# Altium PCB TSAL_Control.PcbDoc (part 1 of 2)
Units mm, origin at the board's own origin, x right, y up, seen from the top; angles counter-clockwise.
Board outline 110 x 55.6 mm, 4 copper layers (Top Layer, GND, PWR, Bottom Layer), stack 1.488 mm thick; 121 components, 67 nets, 352 pads, 66 vias.
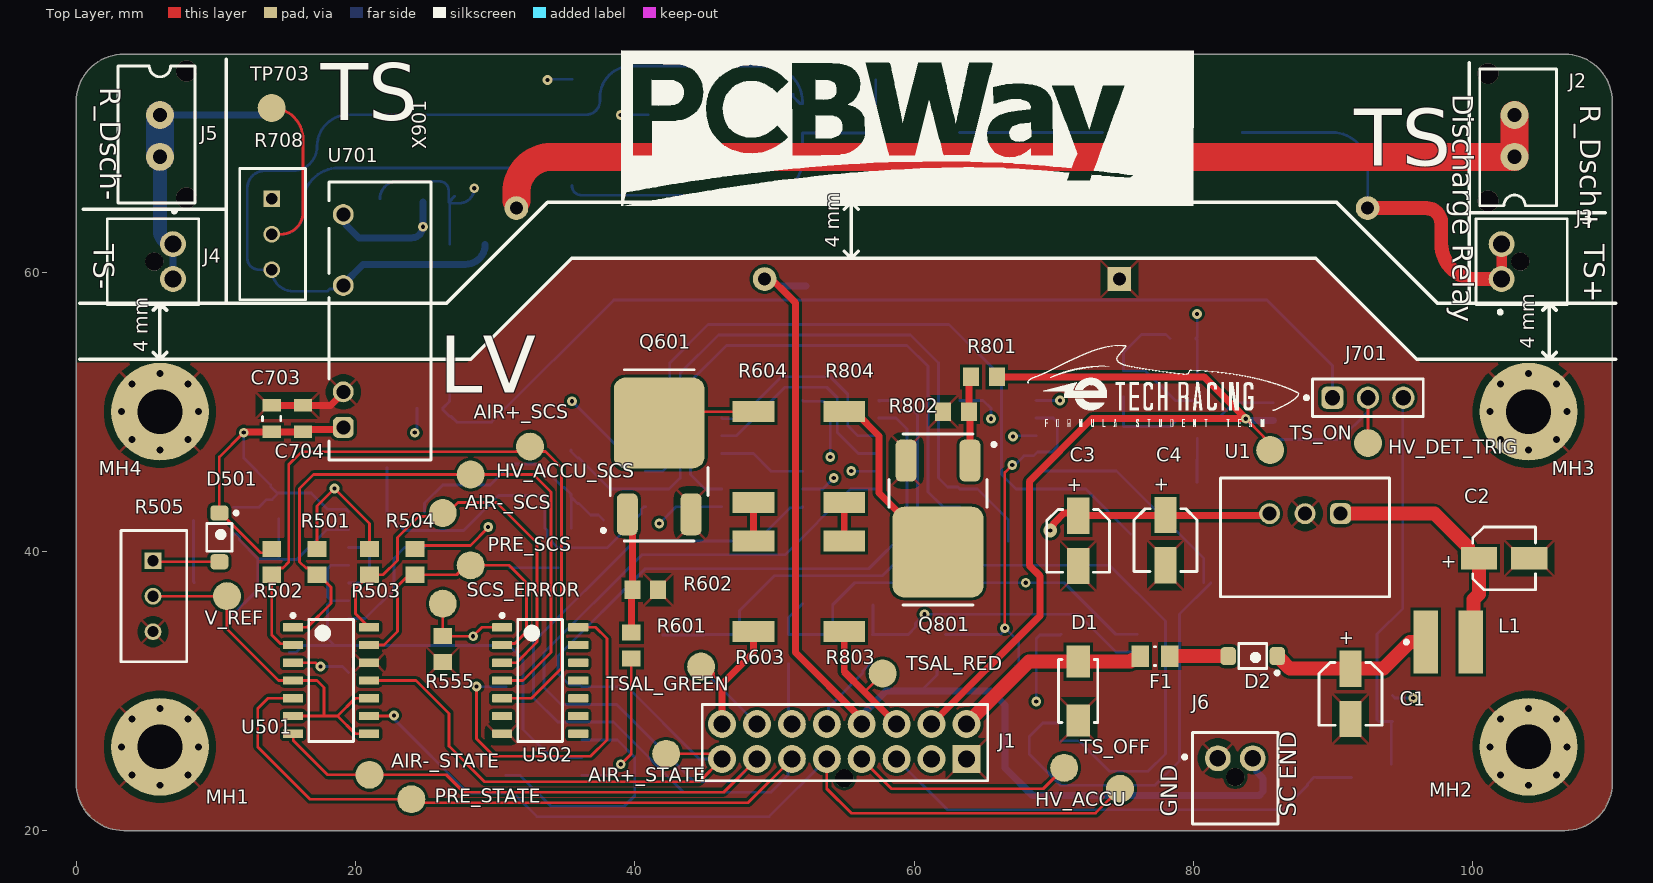
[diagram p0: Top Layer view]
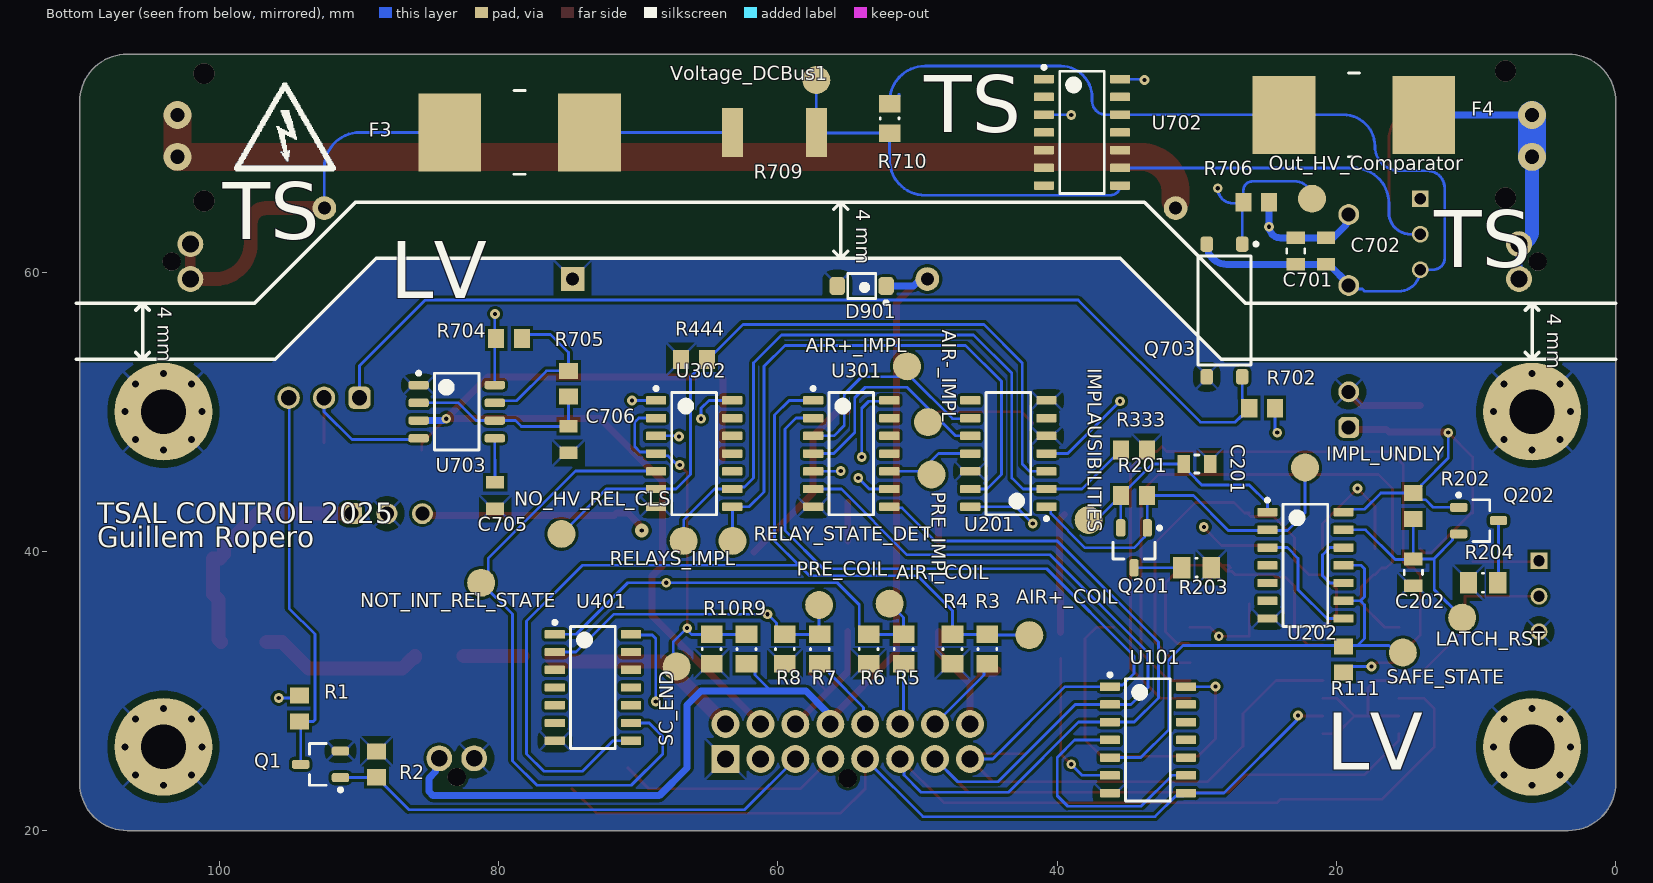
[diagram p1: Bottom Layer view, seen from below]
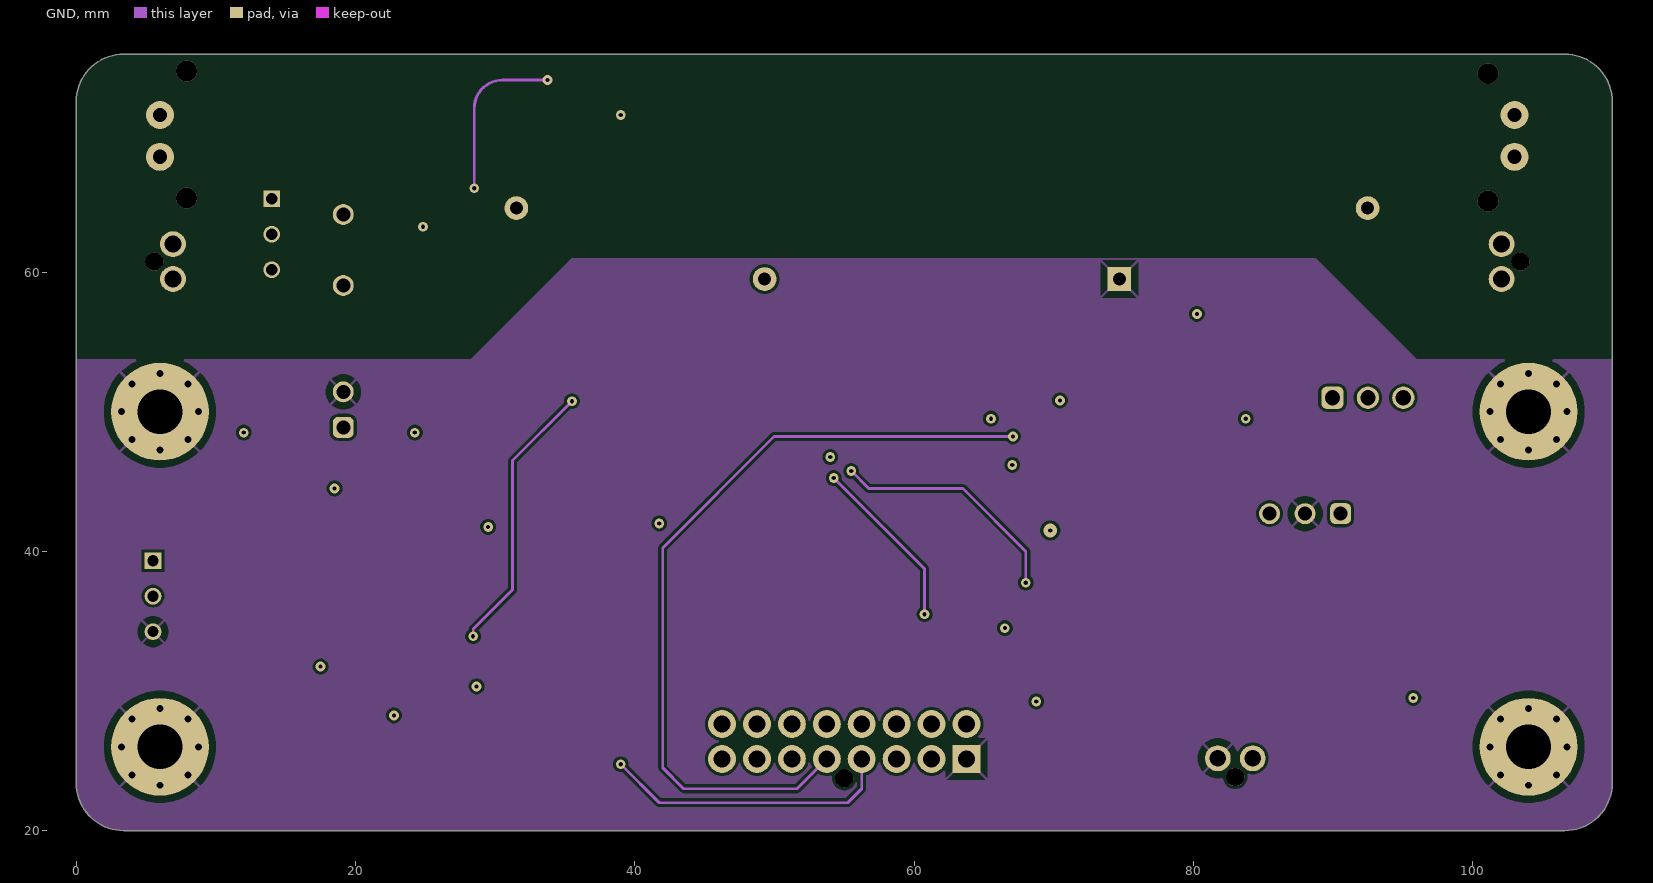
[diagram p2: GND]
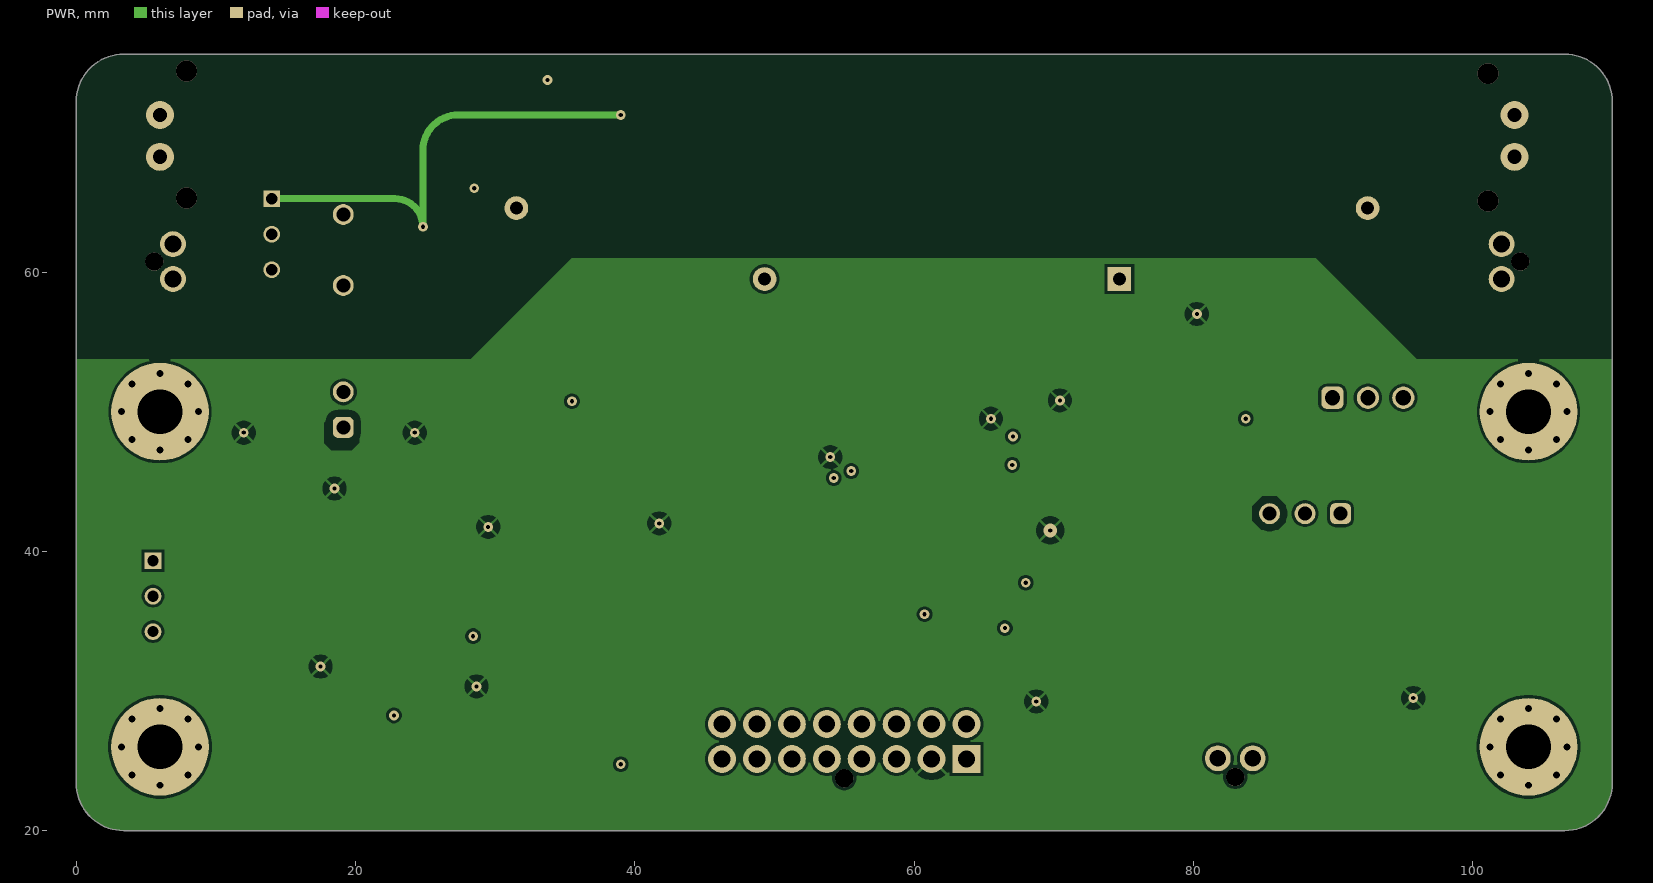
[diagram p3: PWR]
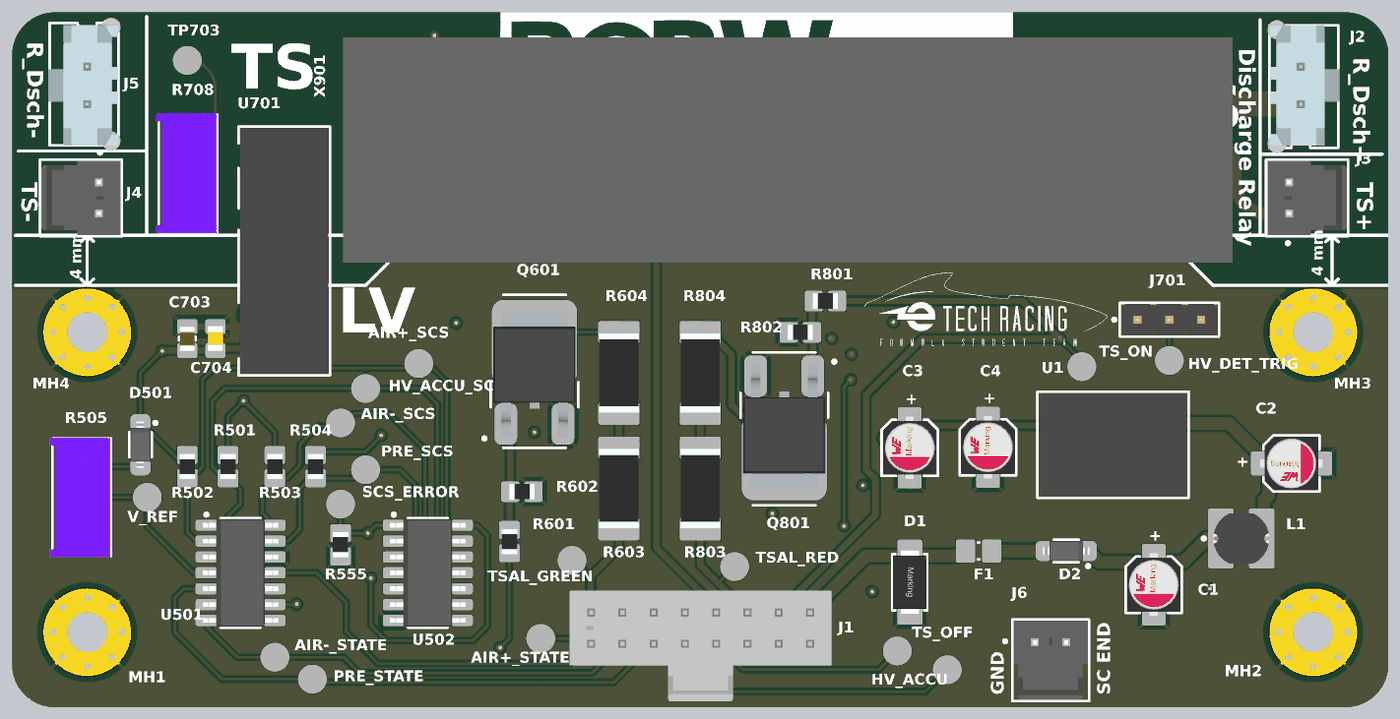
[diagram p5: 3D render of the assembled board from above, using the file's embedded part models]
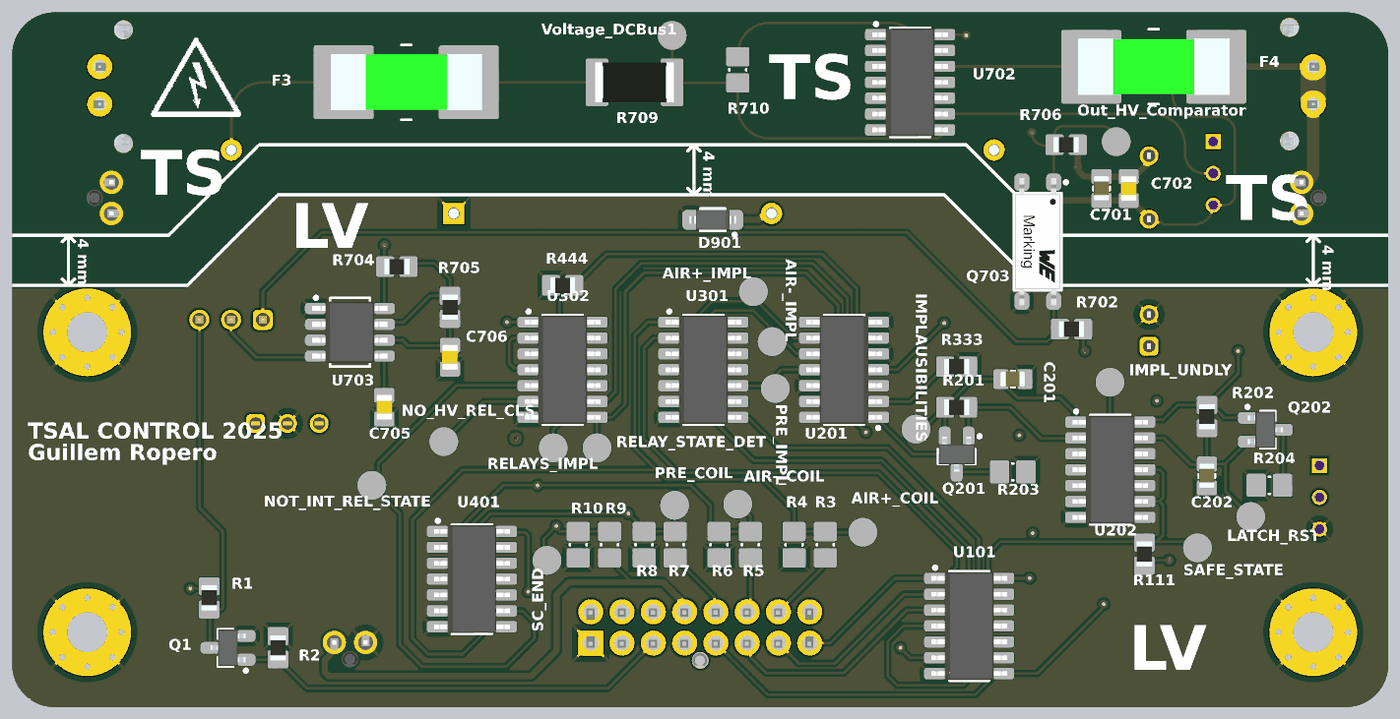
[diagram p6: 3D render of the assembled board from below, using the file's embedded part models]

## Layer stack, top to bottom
Top Solder: solder mask 0.01, Solder Resist, Dk 3.5
Top Layer: signal copper 0.035
Dielectric 2: prepreg 0.1, PP-006, Dk 4.1
GND: signal copper 0.009
Dielectric 6: prepreg 0.1, PP-006, Dk 4.1
Dielectric 1: dielectric 1, FR-4, Dk 4.8
Dielectric 7: prepreg 0.1, PP-006, Dk 4.1
PWR: signal copper 0.009
Dielectric 3: prepreg 0.1, PP-006, Dk 4.1
Bottom Layer: signal copper 0.035
Bottom Solder: solder mask 0.01, Solder Resist, Dk 3.5

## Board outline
0,23.414 0,72 0,72.186 cw(c3.414,72.186) 3.414,75.6 106.5,75.6 106.586,75.6 cw(c106.586,72.186) 110,72.186 110,72 110,23.414 cw(c106.586,23.414) 106.586,20 106.5,20 3.414,20 cw(c3.414,23.414)

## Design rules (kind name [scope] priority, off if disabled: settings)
Clearance Clearance_TS-LVS [InNetClass('TS') vs InNetClass('LVS')] p1: gap=4 ignorepadtopadclearanceinfootprint=FALSE
Clearance Clearance_std [All] p2: gap=0.2 ignorepadtopadclearanceinfootprint=FALSE
ComponentClearance [All] p1: gap=0.2 collisioncheckmode=3 verticalgap=0.2 showdistances=FALSE
HoleSize [All] p1: absolutevalues=TRUE maxlimit=4 minlimit=0.2 maxpercent=80.000 minpercent=20.000
PasteMaskExpansion [All] p1: expansion=0.15
PlaneClearance [All] p1: clearance=0.5
PlaneConnect [All] p1: planeconnectstyle=Relief reliefexpansion=0.5 reliefentries=4 reliefconductorwidth=0.2 reliefairgap=0.2
PolygonConnect [All] p1: connectstyle=Relief reliefconductorwidth=0.2 reliefentries=4 polygonreliefangle="45 Angle" airgapwidth=0.5
RoutingVias [All] p1: holewidth=0.3 width=0.7 viastyle="Through Hole" minholewidth=0.2 minwidth=0.5 maxholewidth=4 maxwidth=8
SilkToSilkClearance [All] p1: silktosilkclearance=0
SilkToSolderMaskClearance [IsPad] p1: minsilkscreentomaskgap=0.1 clearancetoexposedcopper=TRUE
SolderMaskExpansion [All] p1: expansion=0.1 istentingtop=FALSE
UnRoutedNet [All] p1: checkbadconnections=TRUE
Width [All] p1: maxlimit=3 minlimit=0.2 preferedwidth=0.5
22 further rules are at their usual default settings.

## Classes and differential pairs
component class Discharge_circuit: D901 X901
component class "TSAL Red": C701 C702 C703 C704 C705 C706 HV_DET_TRIG J701 Out_HV_Comparator Q703 R702 R704 R705 R706 R708 R709 R710 TP703 TS_ON U701 U702 U703 Voltage_DCBus1
component class "TSAL Green": AIR+_COIL AIR+_STATE AIR-_COIL AIR-_STATE HV_ACCU PRE_COIL PRE_STATE R111 SC_END TS_OFF U101
component class "Relay Implausibility": AIR+_IMPL AIR-_IMPL PRE_IMPL R333 RELAY_STATE_DET RELAYS_IMPL U301 U302
component class "Red Driver": Q801 R801 R802 R803 R804 TSAL_RED
component class Implausibilities: C201 C202 IMPL_UNDLY IMPLAUSIBILITIES LATCH_RST Q201 Q202 R201 R202 R203 R204 SAFE_STATE U201 U202
component class TSAL_Control: C1 C2 C3 C4 D1 D2 F1 F3 F4 F_DC_BUS1 F_DC_BUS? F_TS-? J1 J2 J3 J4 J5 J6 J_TS+_DC_BUS1 J_TS+_DC_BUS? J_TS- L1 MH1 MH2 MH3 MH4 Q1 R1 R2 R3 R4 R5 R6 R7 R8 R9 R10 U1
component class SCS: AIR+_SCS AIR-_SCS D501 HV_ACCU_SCS PRE_SCS R501 R502 R503 R504 R505 R555 SCS_ERROR U501 U502 V_REF
component class "EV 4.10.14": NO_HV_REL_CLS NOT_INT_REL_STATE R444 U401
component class "Green Driver": Q601 R601 R602 R603 R604 TSAL_GREEN

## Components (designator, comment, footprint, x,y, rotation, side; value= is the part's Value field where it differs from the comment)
AIR+_COIL "TestPoint" TestPoint 42,34 r90 bottom (schematic designator TP106)
AIR+_IMPL "TestPoint" TestPoint 50.75,53.25 r90 bottom (schematic designator TP301)
AIR+_SCS "TestPoint" TestPoint 32.5,47.5 r90 top (schematic designator TP503)
AIR+_STATE "TestPoint" TestPoint 42.25,25.5 r90 top (schematic designator TP102)
AIR-_COIL "TestPoint" TestPoint 52,36.25 r90 bottom (schematic designator TP108)
AIR-_IMPL "TestPoint" TestPoint 49.25,49.25 r90 bottom (schematic designator TP302)
AIR-_SCS "TestPoint" TestPoint 26.25,42.75 r90 top (schematic designator TP504)
AIR-_STATE "TestPoint" TestPoint 21,24 r90 top (schematic designator TP104)
C1 "C10u-35V-Electrolytic" 865080540004-Footprint-1 91.25,29.8 r90 top value=10µF
C2 "C10u-35V-Electrolytic" 865080540004-Footprint-1 102.25,39.5 r180 top value=10µF
C3 "C10u-35V-Electrolytic" 865080540004-Footprint-1 71.75,40.75 r90 top value=10µF
C4 "C10u-35V-Electrolytic" 865080540004-Footprint-1 78,40.8 r90 top value=10µF
C201 "C10u-16V-0805FNPC-X5R" C0805FNPC-R 30,46.25 r180 bottom value=10µF
C202 "C10u-16V-0805FNPC-X5R" C0805FNPC-R 14.5,38.5 r270 bottom value=10µF
C701 "C1u-50V-0805FNPC-X7R" C0805FNPC-R 22.921,61.5 r270 bottom value=1µF
C702 "C100n-16V-0805" WCAP-CSGP_0805_L2W1.25H0.8_Reflow 20.75,61.5 r270 bottom
C703 "C1u-50V-0805FNPC-X7R" C0805FNPC-R 14,49.5 r90 top value=1µF
C704 "C100n-16V-0805" WCAP-CSGP_0805_L2W1.25H0.8_Reflow 16.25,49.5 r90 top
C705 "C100n-16V-0805" WCAP-CSGP_0805_L2W1.25H0.8_Reflow 80.25,44 r270 bottom value=100nF
C706 "C22u-25V-0805" WCAP-CSGP_0805_L2W1.25H0.8_Reflow 75,48 r270 bottom value=22uF
D1 "TVS_33V_400W" WE-TVSP_DO-214AC_Bidirectional 71.75,30 r270 top
D2 "DSC-0.5/30-SOD123" DSC-SOD123 84.25,32.5 r180 top
D501 "DZ-0.01/75-SOD-123" DSC-SOD123 10.25,41 r270 top
D901 "DSC-0.5/30-SOD123" DSC-SOD123 54,59 r0 bottom
F1 "MFU0805FF00500P500" 0805 77.25,32.5 r270 top value=0.5A-50V
F3 "Fuse_1A_600V" Fuse_485001 78.5,70 r0 bottom
F4 "Fuse_1A_600V" Fuse_485001 18.75,71.25 r180 bottom
HV_ACCU "TestPoint" TestPoint 74.75,23 r90 top (schematic designator TP105)
HV_ACCU_SCS "TestPoint" TestPoint 28.25,45.5 r90 top (schematic designator TP502)
HV_DET_TRIG "TestPoint" TestPoint 92.5,47.75 r90 top (schematic designator TP704)
IMPL_UNDLY "TestPoint" TestPoint 22.25,46 r90 bottom (schematic designator TP201)
IMPLAUSIBILITIES "TestPoint" TestPoint 37.75,42.25 r90 bottom (schematic designator TP202)
J1 "J_NanoFit_2x8_V" J_NanoFit_2x8_V 55,30 r180 top
J2 "J_MicroFit_2x1" J_MicroFit_2x1 103,68.25 r270 top
J3 "J_NanoFit_1x2" FP-105309-1102-MFG 103.5,60.75 r90 top
J4 "J_NanoFit_1x2" FP-105309-1102-MFG 5.5,60.75 r270 top
J5 "J_MicroFit_2x1" J_MicroFit_2x1 6,71.25 r90 top
J6 "J_NanoFit_1x2" FP-105309-1102-MFG 83,23.75 r0 top
J701 "3Pin-Pinheader" 61300311121 92.5,51 r0 top
L1 "7447730" WE-PD2_4532 98.25,33.5 r0 top value=1uH
LATCH_RST "TestPoint" TestPoint 11,35.25 r90 bottom (schematic designator TP203)
MH1 "Mounting_Hole_M3" Mounting_Hole_M3 6,26 r0 top
MH2 "Mounting_Hole_M3" Mounting_Hole_M3 104,26 r0 top
MH3 "Mounting_Hole_M3" Mounting_Hole_M3 104,50 r0 top
MH4 "Mounting_Hole_M3" Mounting_Hole_M3 6,50 r0 top
NO_HV_REL_CLS "TestPoint" TestPoint 75.5,41.25 r180 bottom (schematic designator TP402)
NOT_INT_REL_STATE "TestPoint" TestPoint 81.25,37.75 r90 bottom (schematic designator TP401)
Out_HV_Comparator "TestPoint" TestPoint 21.75,65.25 r90 bottom (schematic designator TP702)
PRE_COIL "TestPoint" TestPoint 57.05,36.158 r90 bottom (schematic designator TP107)
PRE_IMPL "TestPoint" TestPoint 49,45.5 r90 bottom (schematic designator TP303)
PRE_SCS "TestPoint" TestPoint 28.25,39 r90 top (schematic designator TP505)
PRE_STATE "TestPoint" TestPoint 24,22.25 r90 top (schematic designator TP103)
Q1 "TRT-NCH-8/40-SQ" TRT-NCH-3/35-CPH 92.75,24.75 r0 bottom
Q201 "TRT-PCH-2/30-BSS" TRT-PCH-2/30-BSS 34.5,40.25 r270 bottom
Q202 "TRT-PCH-2/30-BSS" TRT-PCH-2/30-BSS 9.825,42.2 r180 bottom
Q601 "TRT-NCH-31/100" TRT-NCH-D2PAK 41.75,46.75 r0 top
Q703 "Optocoupler" WL-OCPT_LSOP4 28.02,57.25 r270 bottom
Q801 "TRT-NCH-31/100" TRT-NCH-D2PAK 61.714,42.4 r180 top
R1 "R10k-0805FTK" R0805FTK 94.25,28.75 r270 bottom value=10k
R2 "R10k-0805FTK" R0805FTK 88.75,24.75 r90 bottom value=10k
R3 "R12K4-0805-0.125W" 0805 45,33 r180 bottom value=12.4k
R4 "R8.2K_0805_0.125W" 0805 47.5,33 r0 bottom value=8.2k
R5 "R12K4-0805-0.125W" 0805 51,33 r180 bottom value=12.4k
R6 "R8.2K_0805_0.125W" 0805 53.5,33 r0 bottom value=8.2k
R7 "R12K4-0805-0.125W" 0805 57,33 r180 bottom value=12.4k
R8 "R8.2K_0805_0.125W" 0805 59.5,33 r0 bottom value=8.2k
R9 "R12K4-0805-0.125W" 0805 62.25,33 r180 bottom value=12.4k
R10 "R8.2K_0805_0.125W" 0805 64.75,33 r0 bottom value=8.2k
R111 "R470-0805FTK" R0805FTK 19.5,32.25 r270 bottom value=470
R201 "R10k-0805FTK" R0805FTK 34.5,44 r0 bottom value=10k
R202 "R10k-0805FTK" R0805FTK 14.5,43.25 r270 bottom value=10k
R203 "R1K-0805-0.5W" 0805 30.021,38.829 r270 bottom value=1k
R204 "R1K-0805-0.5W" 0805 9.5,37.75 r90 bottom value=1k
R333 "R470-0805FTK" R0805FTK 34.5,47.25 r0 bottom value=470
R444 "R470-0805FTK" R0805FTK 66,53.75 r180 bottom value=470
R501 "R1k-0805FTK" R0805FTK 17.25,39.25 r270 top value=1k
R502 "R1k-0805FTK" R0805FTK 14,39.25 r270 top value=1k
R503 "R1k-0805FTK" R0805FTK 21,39.25 r270 top value=1k
R504 "R1k-0805FTK" R0805FTK 24.25,39.25 r270 top value=1k
R505 "R1k-VTR" R1k-VTR 5.5,36.79 r0 top value=1k
R555 "R470-0805FTK" R0805FTK 26.25,33 r90 top value=470
R601 "R100-0805FTK" R0805FTK 39.75,33.25 r90 top value=100
R602 "R1k-0805FTK" R0805FTK 40.75,37.25 r0 top value=1k
R603 "R15_3521_2W" R_3521 48.5,37.5 r90 top value=15
R604 "R15_3521_2W" R_3521 48.5,46.75 r90 top value=15
R702 "R10k-0805FTK" R0805FTK 25.325,50.25 r0 bottom value=10k
R704 "R100-0805FTK" R0805FTK 79.25,55.25 r180 bottom value=100
R705 "R10k-0805FTK" R0805FTK 75,52 r270 bottom value=10k
R706 "R10k-0805FTK" R0805FTK 25.75,65 r0 bottom value=10k
R708 "R10k-VTR" R10k-VTR 14,62.71 r0 top value=10k
R709 "R2M-2512FTK" R2512FTK 60.25,70 r180 bottom
R710 "R51k_0805" 0805 52,71 r180 bottom value=51k
R801 "R100-0805FTK" R0805FTK 65,52.5 r180 top value=100
R802 "R1k-0805FTK" R0805FTK 63,50 r180 top value=1k
R803 "R15_3521_2W" R_3521 55,37.5 r90 top value=15
R804 "R15_3521_2W" R_3521 55,46.75 r90 top value=15
RELAY_STATE_DET "TestPoint" TestPoint 63.25,40.75 r90 bottom (schematic designator TP304)
RELAYS_IMPL "TestPoint" TestPoint 66.75,40.75 r90 bottom (schematic designator TP305)
SAFE_STATE "TestPoint" TestPoint 15.25,32.75 r90 bottom (schematic designator TP204)
SC_END "TestPoint" TestPoint 67.25,31.75 r90 bottom (schematic designator TP109)
SCS_ERROR "TestPoint" TestPoint 26.25,36.25 r90 top (schematic designator TP506)
TP703 "TestPoint" TestPoint 14,71.75 r90 top
TS_OFF "TestPoint" TestPoint 70.75,24.5 r90 top (schematic designator TP101)
TS_ON "TestPoint" TestPoint 85.5,47.25 r90 top (schematic designator TP701)
TSAL_GREEN "TestPoint" TestPoint 44.75,31.75 r90 top (schematic designator TP601)
TSAL_RED "TestPoint" TestPoint 57.75,31.25 r90 top (schematic designator TP801)
U1 "DCDC-36V/12V-1A" WPME-FDSM_SIP-3_L11.6W8H10.4 88,41 r180 top
U101 "CD4073BM" D0014A_N 33.5,26.5 r180 bottom
U201 "CD4072BM" D0014A_N 43.5,47 r0 bottom
U202 "CD4011BM" D0014A_N 22.225,39 r180 bottom
U301 "CD4070BM" D0014A_N 54.75,47 r180 bottom
U302 "CD4073BM" D0014A_N 66,47 r180 bottom
U401 "CD4023BM" D0014A_N 73.25,30.25 r180 bottom
U501 "LM339D" D0014A_N 18.25,30.75 r0 top
U502 "CD4072BM" D0014A_N 33.225,30.75 r0 top
U701 "DCDC_ISO_12VIN_5VOUT" WPME-FISM_SIP-7_L19.65W7.05H10.16 21.75,56.5 r90 top
U702 "LM339D" D0014A_N 38.225,70 r180 bottom
U703 "Timer_SA555" Timer_SA555 83,50 r180 bottom
V_REF "TestPoint" TestPoint 10.798,36.79 r90 top (schematic designator TP501)
Voltage_DCBus1 "TestPoint" TestPoint 57.25,73.75 r90 bottom (schematic designator TP705)
X901 "HV-Relay-SPST-NC-24V" HV-Relay-SPST-NC-24V 31.52,64.58 r0 top

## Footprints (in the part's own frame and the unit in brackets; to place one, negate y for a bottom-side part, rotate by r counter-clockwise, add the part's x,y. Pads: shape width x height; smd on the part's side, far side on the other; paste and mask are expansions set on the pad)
0805 [mm] "Chip Resistor, 2-Leads, Body 2,60x1,50mm, IPC Medium Density"
  rect 1.55x1.25 smd: 1(0,-1.05) 2(0,1.05)
  silkscreen extent -0.67,-0.05 0.67,0.05, body extent -0.75,-1.3 0.75,1.3, height 0.6
61300311121 [mm] "Pin Header, pitch 2.54 mm, THT, Vertical, single row, 3p"
  rrect50% 1.6x1.6 hole 1.1: 1(-2.54,0)
  round 1.6 hole 1.1: 2(0,0) 3(2.54,0)
  silkscreen extent -4.53,-1.35 3.96,1.35, body extent -3.81,-1.27 3.81,1.27, height 8.57
865080540004-Footprint-1 [mm]
  rect 2.6x1.6 smd: 1(1.8,0) 2(-1.8,0)
  silkscreen extent -2.25,-2.25 2.25,2.25, body extent -2.5,-2.15 2.5,2.15, height 5.5
C0805FNPC-R [mm]
  rect 0.9x1.3 smd: 1(-0.95,0) 2(0.95,0)
  silkscreen extent -0.15,-0.65 0.15,0.65, body extent -1.03,-0.63 0.97,0.63, height 0.96
D0014A_N [mm] "SOIC, 14-Leads, Body 8.75x4mm, Pitch 1.27mm, IPC Medium Density"
  rrect17% 1.45x0.6 smd: 1(-2.725,3.81) 2(-2.725,2.54) 3(-2.725,1.27) 4(-2.725,0) 5(-2.725,-1.27) 6(-2.725,-2.54) 7(-2.725,-3.81) 8(2.725,-3.81) 9(2.725,-2.54) 10(2.725,-1.27) 11(2.725,0) 12(2.725,1.27) 13(2.725,2.54) 14(2.725,3.81)
  silkscreen extent -2.85,-4.38 1.6,4.78, body extent -3.02,-4.32 3.02,4.32, height 1.59
DSC-SOD123 [mm] "SOIC, 2-Leads, Body 1,60x2,69mm, Pitch 1,27mm, IPC Low Density"
  rrect50% 1.1x1.3 smd: A(1.75,0) K(-1.75,0)
  silkscreen extent -1.88,-0.9 1,1.32, body extent -1.86,-0.8 1.86,0.8, height 1.36
FP-105309-1102-MFG [mm]
  round 1.85 hole 1.2 paste-2539.97 mask+0: 1(-1.25,1.43) 2(1.25,1.43)
  round 1.3 hole 1.3 unplated paste-2539.97 mask+0: ""(0,0.09)
  silkscreen extent -3.75,-3.27 3.07,3.27, body extent -3.17,-3.37 3.17,3.37, height 0.25
Fuse_485001 [mm]
  rect 4.5x5.6 smd: 1(-5,0) 2(5,0)
  silkscreen extent -0.4,-3 0.4,3, body extent -6.05,-2.25 6.05,2.25, height 4.5
HV-Relay-SPST-NC-24V [mm]
  round 1.7 hole 0.94: 1(0,0) 2(17.78,-5.08) 4(60.96,0)
  rect 1.7x1.7 hole 0.94: 3(43.18,-5.08)
  body extent -5.08,-9.02 66.04,9.01, height 19.15
J_MicroFit_2x1 [mm]
  round 2 hole 1.02: 1(0,0) 2(-3,0)
  silkscreen extent -6.3,-2.5 3.5,3, body extent -6.32,-2.47 3.32,3.1, height 10
J_NanoFit_2x8_V [mm]
  round 2 hole 1.2: 1(8.75,4.87) 2(6.25,4.87) 3(3.75,4.87) 4(1.25,4.87) 5(-1.25,4.87) 6(-3.75,4.87) 7(-6.25,4.87) 9(8.75,2.369) 10(6.25,2.369) 11(3.75,2.369) 12(1.25,2.369) 13(-1.25,2.369) 14(-3.75,2.369) 15(-6.25,2.369) 16(-8.75,2.369)
  rect 2x2 hole 1.2: 8(-8.75,4.87)
  round 1.3 hole 1.3: A(0,6.25)
  silkscreen extent -10.27,0.97 10.17,6.43, body extent -10.5,0.68 10.44,9.53, height 10.18
Mounting_Hole_M3 [mm]
  round 7 hole 3.2: 1(0,0)
R1k-VTR [mm]
  rect 1.2x1.2 hole 0.8: 1(0,2.54)
  round 1.2 hole 0.8: 2(0,-2.54) 3(0,0)
  silkscreen extent -2.29,-4.7 2.41,4.7, body extent -2.49,-4.78 2.34,4.78, height 11.09
R10k-VTR [mm]
  rect 1.2x1.2 hole 0.8: 1(0,2.54)
  round 1.2 hole 0.8: 2(0,-2.54) 3(0,0)
  silkscreen extent -2.29,-4.7 2.41,4.7, body extent -2.49,-4.78 2.34,4.78, height 11.09
R0805FTK [mm] "Chip Resistor, 2-Leads, Body 2,00x1,25mm, IPC Medium Density"
  rect 1.15x1.35 smd: 1(-0.925,0) 2(0.925,0)
  body extent -1,-0.63 1,0.63, height 0.65
R2512FTK [mm]
  rect 1.5x3.5 smd: 1(-3,0) 2(3,0)
  body extent -3.15,-1.6 3.15,1.6, height 0.66
R_3521 [mm]
  rect 1.5x3 smd: 1(-3.25,0) 2(3.25,0)
  body extent -3.17,-1.6 3.17,1.6, height 0.65
TestPoint [mm]
  round 2 smd: 1(0,0)
Timer_SA555 [mm] "SOIC, 8-Leads, Body 4,90x3,90mm, Pitch 1,27mm, IPC Medium Density"
  rrect50% 1.45x0.6 smd: 1(-2.725,1.905) 2(-2.725,0.635) 3(-2.725,-0.635) 4(-2.725,-1.905) 5(2.725,-1.905) 6(2.725,-0.635) 7(2.725,0.635) 8(2.725,1.905)
  silkscreen extent -2.85,-2.75 1.6,2.88, body extent -3.01,-2.45 3.01,2.45, height 1.63
TRT-NCH-3/35-CPH [mm] "SOT23, 3-Leads, Body 2,90x2,80mm, Pitch 0,95mm, IPC Low Density"
  rrect50% 1.25x0.65 smd: D(1.425,0) G(-1.425,0.95) S(-1.425,-0.95)
  silkscreen extent -1.55,-1.5 0.8,1.95, body extent -1.4,-1.45 1.4,1.45, height 1.06
TRT-NCH-D2PAK [mm] "SOT23, 3-Leads, Body 2,90x2,80mm, Pitch 0,95mm, IPC Low Density"
  rrect25% 6.5x6.5 smd: D(0,2.45)
  rrect50% 1.5x3 smd: G(-2.286,-4.1) S(2.286,-4.1)
  silkscreen extent -4.12,-6 3.5,6.25, body extent -3.29,-5.12 3.29,4.8, height 2.29
TRT-PCH-2/30-BSS [mm] "SOT23, 3-Leads, Body 2,90x2,80mm, Pitch 0,95mm, IPC Low Density"
  rrect50% 1.25x0.65 smd: D(1.425,0) G(-1.425,0.95) S(-1.425,-0.95)
  silkscreen extent -1.55,-1.5 0.8,1.95, body extent -1.4,-1.45 1.4,1.45, height 1.06
WCAP-CSGP_0805_L2W1.25H0.8_Reflow [mm] "Ceramic Capacitors, body 2x1.25mm"
  rect 0.9x1.3 smd: 1(-0.95,0) 2(0.95,0)
  body extent -1,-0.62 1,0.63, height 0.8
WE-PD2_4532 [mm] "SMD Power Inductor, 2-Leads, body 4.5x4mm"
  rect 1.75x4.5 smd: 1(-1.625,0) 2(1.625,0)
  silkscreen extent -3.12,-0.12 -2.87,0.12, body extent -2.25,-2 2.25,2, height 3.22
WE-TVSP_DO-214AC_Bidirectional [mm] "Power TVS Diode, 2-Leads. body 4.24x2.67mm"
  rect 2.3x1.7 smd: 1(-2.1,0) 2(2.1,0)
  silkscreen extent -2.25,-1.4 2.25,1.4, body extent -2.56,-1.33 2.56,1.34, height 2.24
WL-OCPT_LSOP4 [mm] "Optocoupler Phototransistor, body 7.6x3.6mm"
  rrect50% 1.1x0.9 smd: 1(-4.75,1.27) 2(-4.75,-1.27) 3(4.75,-1.27) 4(4.75,1.27)
  silkscreen extent -4.87,-1.9 3.9,2.37, body extent -5.1,-1.8 5.1,1.8, height 2.1
WPME-FDSM_SIP-3_L11.6W8H10.4 [mm] "Fixed Step Down Regulator Module, SIP-3, body 11.60x80mm"
  rrect50% 1.5x1.5 hole 1: 1(-2.54,-1.7)
  round 1.5 hole 1: 2(0,-1.7) 3(2.54,-1.7)
  silkscreen extent -6.05,-4.25 6.05,4.25, body extent -5.8,-4 5.8,4, height 10.45
WPME-FISM_SIP-7_L19.65W7.05H10.16 [mm] "Power Module, SIP7, body 19.65x7.05mm"
  rrect50% 1.5x1.5 hole 1 paste-0.1: 1(-7.62,2.625)
  round 1.5 hole 1 paste-0.1: 2(-5.08,2.625) 3(2.54,2.625) 4(7.62,2.625)
  silkscreen extent -9.95,-3.65 9.95,3.65, body extent -9.82,-3.52 9.82,3.52, height 10.16

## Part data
AIR+_COIL AIR+_IMPL AIR+_SCS AIR+_STATE AIR-_COIL AIR-_IMPL AIR-_SCS AIR-_STATE HV_ACCU HV_ACCU_SCS HV_DET_TRIG IMPL_UNDLY IMPLAUSIBILITIES LATCH_RST NO_HV_REL_CLS NOT_INT_REL_STATE Out_HV_Comparator PRE_COIL PRE_IMPL PRE_SCS PRE_STATE RELAY_STATE_DET RELAYS_IMPL SAFE_STATE SC_END SCS_ERROR TP703 TS_OFF TS_ON TSAL_GREEN TSAL_RED V_REF Voltage_DCBus1: library part CMP-00042-1, "Test Point 1x1 mm"
C1 C2 C3 C4: library part CMP-001-00019-3, "WCAP-ASLI Aluminum Electrolytic Capacitors", Case/Package=Radial, Max Operating Temperature=105°C, Min Operating Temperature=-55°C, Ripple Current=90mA, Tolerance=20%, Voltage Rating=35V
C201 C202: library part CMP-00055-8, "Multilayer Ceramic Capacitor, Wcap-Csgp Series, 10 F, 20%, X5R, 16 V, 0805 [2012 Metric] Rohs Compliant: Yes", Case Code (Metric)=2012, Case/Package=0805, Dielectric=X5R, Manufacturer 1="Wurth Electronics", Manufacturer Part Number 1=885012107014, Max Operating Temperature=85°C, Min Operating Temperature=-55°C, Tolerance=20%, Voltage Rating=16V
C701 C703: library part CMP-00052-2, "Multilayer Ceramic Capacitor, Wcap-Csgp Series, 1 F, 10%, X7R, 50 V, 0805 [2012 Metric] Rohs Compliant: Yes", Case Code (Metric)=2012, Case/Package=0805, Dielectric=X7R, Manufacturer 1="Wurth Electronics", Manufacturer Part Number 1=885012207103, Max Operating Temperature=85°C, Min Operating Temperature=-55°C, Tolerance=10%, Voltage Rating=50V
C702 C704 C705: library part CMP-001-00008-6, "Ceramic Capacitor, Multilayer, Ceramic, 16V, 10% +Tol, 10% -Tol, X7R, 15% TC, 0.1uF, Surface Mount, 0805", Capacitor Type=Ceramic
C706: library part CMP-001-00017-4, "885012107019"
D1: library part CMP-004-00003-1, "Trans Voltage Suppressor Diode, 400W, Bidirectional, 1 Element, Silicon, DO-214AC", Max Operating Temperature=150°C, Min Operating Temperature=-65°C
D2 D901: library part CMP-00165-2, "VR=30V IF=500mA 30pF P=410mW", Average Rectified Current=500mA, Forward Voltage=430mV, Max Forward Surge Current (Ifsm)=5.5A, Max Repetitive Reverse Voltage (Vrrm)=30V, Max Reverse Current=130uA, Package Quantity=1
D501: library part CMP-00159-1, "Diode Zener Single 10V 2% 500mW 2-Pin SOD-123 T/R", Case/Package=3000, Manufacturer=Vishay, Manufacturer Part Number=MMSZ5240C-HE3-08, Max Operating Temperature=150°C, Max Power Dissipation=500mW, Max Reverse Leakage Current=3uA, Min Operating Temperature=-55°C, Tolerance=2%, Zener Current=20mA, Zener Voltage=10V
F1: library part CMP-001-00020-3, "Fuse, 24 Milliohms to 660 Milliohms (Cold) @ 0.1, 32 V, 0805, 15 C, 35 C", Case/Package=0805, Current Rating=500mA, Max Operating Temperature=125°C, Min Operating Temperature=15°C
F3 F4: library part CMP-00161-2, "Surface Mount Fuses 600V 1A Fast Acting", Case/Package=SMD/SMT, Current Rating=1A, DC Cold Resistance=304.4mR, Manufacturer 1=Littelfuse, Manufacturer Part Number 1=0485001.DR, Max Operating Temperature=125°C, Min Operating Temperature=-55°C, Package Quantity=1, Resistance=0.264, Voltage Rating=600V, Voltage Rating (AC)=250V
J1: library part CMP-00020-3, "Nano-Fit Vertical Header Through Hole 2.50mm Pitch Dual Row 16 Circuits with Kinked Pins Tin (Sn) Plating Black", Insulation Color=Black, Manufacturer 1=Molex, Manufacturer Part Number 1=105310-1116, Max Operating Temperature=105°C, Min Operating Temperature=-40°C
J2 J5: library part CMP-00012-1, "Header 1 Row Vertical Polarizing Peg 2 Pin SMT/Glow Wire Compatible Tin Plate", Manufacturer 1=Molex, Manufacturer Part Number 1=43650-0215
J3 J4 J6: library part CMP-002-00001-2, "Conn HDR 2 POS 2.5mm Solder ST Thru-Hole 2 Terminal 1 Port Nano-Fit Tray"
J701: library part CMP-002-00009-1, "Board Connector, 3 Contact(s), 1 Row(s), Male, Straight, 0.1 inch Pitch, Solder Terminal, Locking, Black Insulator, Plug", Max Operating Temperature=125°C, Min Operating Temperature=-40°C
L1: library part CMP-006-00005-1, "General Purpose Inductor, 1uH, 20%, 1 Element, Nickel-zinc Ferrite-Core, SMD, 1816", Max Current Rating=4A, Max Operating Temperature=125°C, Min Operating Temperature=-40°C, Self Resonant Frequency=110MHz, Tolerance=20%
MH1 MH2 MH3 MH4: library part CMP-00040-2
Q1: library part CMP-00142-1, "Automotive N-channel 40 V (d-s) 175C Mosfet SOT-23", Manufacturer 1=Vishay, Manufacturer Part Number 1=SQ2318BES-T1_GE3
Q201 Q202: library part CMP-00144-2, "Infineon’s highly innovative OptiMOS™ families include p-channel power MOSFETs, SOT-23-3, RoHS", Case/Package=TO-236-3, Continuous Drain Current (ID)=2A, Drain to Source Voltage (Vdss)=30V, Gate to Source Voltage (Vgs)=20V, Input Capacitance=500pF, Manufacturer=Infineon, Manufacturer Part Number=BSS308PEH6327, Max Operating Temperature=150°C, Max Power Dissipation=500mW, Min Operating Temperature=-55°C, Package Quantity=1, Threshold Voltage=-1.5V
Q601 Q801: library part CMP-00139-1, "MOSFET N-CH 100V 31A DPAK", Case/Package=TO-252-3, Continuous Drain Current (ID)=31A, Drain to Source Breakdown Voltage=100V, Drain to Source Resistance=39mR, Gate to Source Voltage (Vgs)=20V, Input Capacitance=1.69nF, Manufacturer 1=Infineon, Manufacturer Part Number 1=IRFR3410TRPBF, Max Operating Temperature=175°C, Max Power Dissipation=3W, Min Operating Temperature=-55°C, Power Dissipation=110W, Threshold Voltage=4V
Q703: library part CMP-00195-1, "Transistor Output Optocoupler. S/N: 140100146000"
R1 R2 R201 R202 R702 R705 R706: library part CMP-00085-4, "BOURNS         CR0805-JW-103ELF            Surface Mount Chip Resistor, Thick Film, CR Series, 10 kohm, 125 mW,  5%, 150 V", Case Code (Metric)=2012, Case/Package=0805, Manufacturer 1=Bourns, Manufacturer Part Number 1=CR0805-JW-103ELF, Max Operating Temperature=155°C, Max Power Dissipation=125mW, Min Operating Temperature=-55°C, Package Quantity=1, Resistance Tolerance=5%, Resistor Type="Thick Film", Temperature Coefficient=200ppm/°C, Voltage Rating=150V, Voltage Rating (DC)=100V
R3 R5 R7 R9: library part CMP-009-00046-1, "Fixed Resistor, Metal Glaze/thick Film, 0.125W, 12400ohm, 150V, 1% +/-Tol, 100ppm/Cel, Surface Mount, 0805", Case/Package=0805, Max Operating Temperature=155°C, Min Operating Temperature=-55°C, Power=125mW, Tolerance=1%
R4 R6 R8 R10: library part CMP-009-00044-2, "Fixed Resistor, Metal Glaze/thick Film, 0.125W, 8200ohm, 150V, 1% +/-Tol, 100ppm/Cel, Surface Mount, 0805", Case/Package=0805, Max Operating Temperature=155°C, Min Operating Temperature=-55°C, Power=125mW, Tolerance=1%
R111 R333 R444 R555: library part CMP-00093-2, "Res Thick Film 0805 470 Ohm 1% 1/8W ±100ppm/°C Molded SMD SMD Paper Tape on Plastic Reel", Case Code (Metric)=2012, Case/Package=0805, Manufacturer 1=Bourns, Manufacturer Part Number 1=CR0805-FX-4700GLF, Max Operating Temperature=155°C, Max Power Dissipation=125mW, Min Operating Temperature=-55°C, Resistance Tolerance=1%, Resistor Type="Thick Film", Temperature Coefficient=100ppm/°C, Voltage Rating=150V
R203 R204: library part CMP-009-00043-2, "Fixed Resistor, Metal Glaze/thick Film, 0.5W, 1000ohm, 150V, 1% +/-Tol, 100ppm/Cel, Surface Mount, 0805", Case/Package=0805, Max Operating Temperature=155°C, Min Operating Temperature=-55°C, Power=500mW, Tolerance=1%
R501 R502 R503 R504 R602 R802: library part CMP-00076-2, "Res Thick Film 0805 1K Ohm 5% 1/8W ±200ppm/°C Molded SMD SMD Paper Tape on Plastic Reel", Case Code (Metric)=2012, Case/Package=0805, Manufacturer 1=Bourns, Manufacturer Part Number 1=CR0805-JW-102ELF, Max Operating Temperature=155°C, Max Power Dissipation=125mW, Min Operating Temperature=-55°C, Package Quantity=1, Resistor Type="Thick Film", Temperature Coefficient=200ppm/°C, Tolerance=5%, Voltage Rating=150V
R505: library part CMP-00071-1, "Res Cermet Trimmer 1K Ohm 10% 1/2W 25(Elec)Turn 2.19mm (9.53 X 4.83 X 11.55mm) Pin Thru-Hole Tube", Color=Blue, Manufacturer=Bourns, Manufacturer Part Number=3296Y-1-102LF, Max Operating Temperature=125°C, Max Power Dissipation=500mW, Min Operating Temperature=-55°C, Package Quantity=50, Resistance Tolerance=10%, Resistor Type=Cermet, Temperature Coefficient=100ppm/°C
R601 R704 R801: library part CMP-00083-2, "Res Thick Film 0805 100 Ohm 1% 1/8W ±100ppm/°C Molded SMD SMD Paper Tape on Plastic Reel", Case Code (Metric)=2012, Case/Package=0805, Manufacturer 1=Bourns, Manufacturer Part Number 1=CR0805-FX-1000ELF, Max Operating Temperature=155°C, Max Power Dissipation=125mW, Min Operating Temperature=-55°C, Package Quantity=1, Resistance Tolerance=1%, Resistor Type="Thick Film", Temperature Coefficient=100ppm/°C, Voltage Rating=150V
R603 R604 R803 R804: library part CMP-00075-6, "Res Thick Film 2512 15 Ohm 1% 2W ±100ppm/C Pad SMD T/R", Case Code (Metric)=6432, Case/Package=2512, Manufacturer 1="TE Connectivity", Manufacturer Part Number 1=352115RFT, Max Operating Temperature=155°C, Max Power Dissipation=2W, Min Operating Temperature=-55°C, Number of Resistors=1, Resistance Tolerance=1%, Resistor Type="Thick Film,Power resistor", Temperature Coefficient=100ppm/°C, Voltage Rating=250V
R708: library part CMP-00072-1, "Trimmer, Cermet, Rest 10 Kilohms, PCB, 25 Turns, Pwr-Rtg 0.5W, 3296 Series", Color=Blue, Insulation Resistance=1GR, Manufacturer=Bourns, Manufacturer Part Number=3296W-1-103LF, Max Operating Temperature=125°C, Max Power Dissipation=500mW, Min Operating Temperature=-55°C, Package Quantity=50, Resistance Tolerance=10%, Resistor Type=Cermet, Temperature Coefficient=100ppm/°C
R709: library part CMP-00108-2, "Current Sense Resistors - SMD 3watts .002ohms 1%", Case Code (Imperial)=2512, Case Code (Metric)=6432, Manufacturer="Vishay Dale", Manufacturer Part Number=WSLP25122L000FEA, Max Operating Temperature=170°C, Min Operating Temperature=-65°C, Package Quantity=2000, Power rating=3W, Resistance=2M, Resistor Type="Metal Strip", Temperature Coefficient=275ppm/°C, Tolerance=1%
R710: library part CMP-009-00018-4, "Fixed Resistor, Metal Glaze/thick Film, 0.125W, 51000ohm, 150V, 1% +/-Tol, 100ppm/Cel, Surface Mount, 0805. ERJ-6ENF5102V", Case/Package=0805, Max Operating Temperature=155°C, Min Operating Temperature=-55°C, Power=125mW, Tolerance=1%
U1: library part CMP-019-00006-1, "Switching Regulator 36V In / 12 V Out, 1A. 173011235"
U101 U302: library part CMP-00213-1, "AND Gate, 4000/14000/40000 Series, 3-Func, 3-Input, CMOS, PDSO14", Case/Package=SOP, Load Capacitance (CL)=50pF, Max Operating Temperature=125°C, Max Supply Voltage=18V, Min Operating Temperature=-55°C, Min Supply Voltage=3V, Nominal Supply Voltage=5V, Package Body Material=Plastic, Package Equivalence Code=SOP14,.25, Package Shape=Rectangular, Package Style="SMALL OUTLINEMeter", Peak Reflow Temperature (Cel)=260°C, Power Supplies=5/15V, Temperature Grade=MILITARY
U201 U502: library part CMP-00217-1, "OR Gate, 4000/14000/40000 Series, 2-Func, 4-Input, CMOS, PDSO14", Case/Package=SOP, Load Capacitance (CL)=50pF, Max Operating Temperature=125°C, Max Supply Voltage=18V, Min Operating Temperature=-55°C, Min Supply Voltage=3V, Nominal Supply Voltage=5V, Package Body Material=Plastic, Package Equivalence Code=SOP14,.25, Package Shape=Rectangular, Package Style="SMALL OUTLINEMeter", Peak Reflow Temperature (Cel)=260°C, Power Supplies=5/15V, Temperature Grade=MILITARY
U202: library part CMP-00211-1, "NAND Gate, 4000/14000/40000 Series, 4-Func, 2-Input, CMOS, PDSO14", Case/Package=SOP, Load Capacitance (CL)=50pF, Max Operating Temperature=125°C, Max Supply Voltage=18V, Min Operating Temperature=-55°C, Min Supply Voltage=3V, Nominal Supply Voltage=5V, Package Body Material=Plastic, Package Equivalence Code=SOP14,.25, Package Shape=Rectangular, Package Style="SMALL OUTLINEMeter", Peak Reflow Temperature (Cel)=260°C, Power Supplies=5/15V, Temperature Grade=MILITARY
